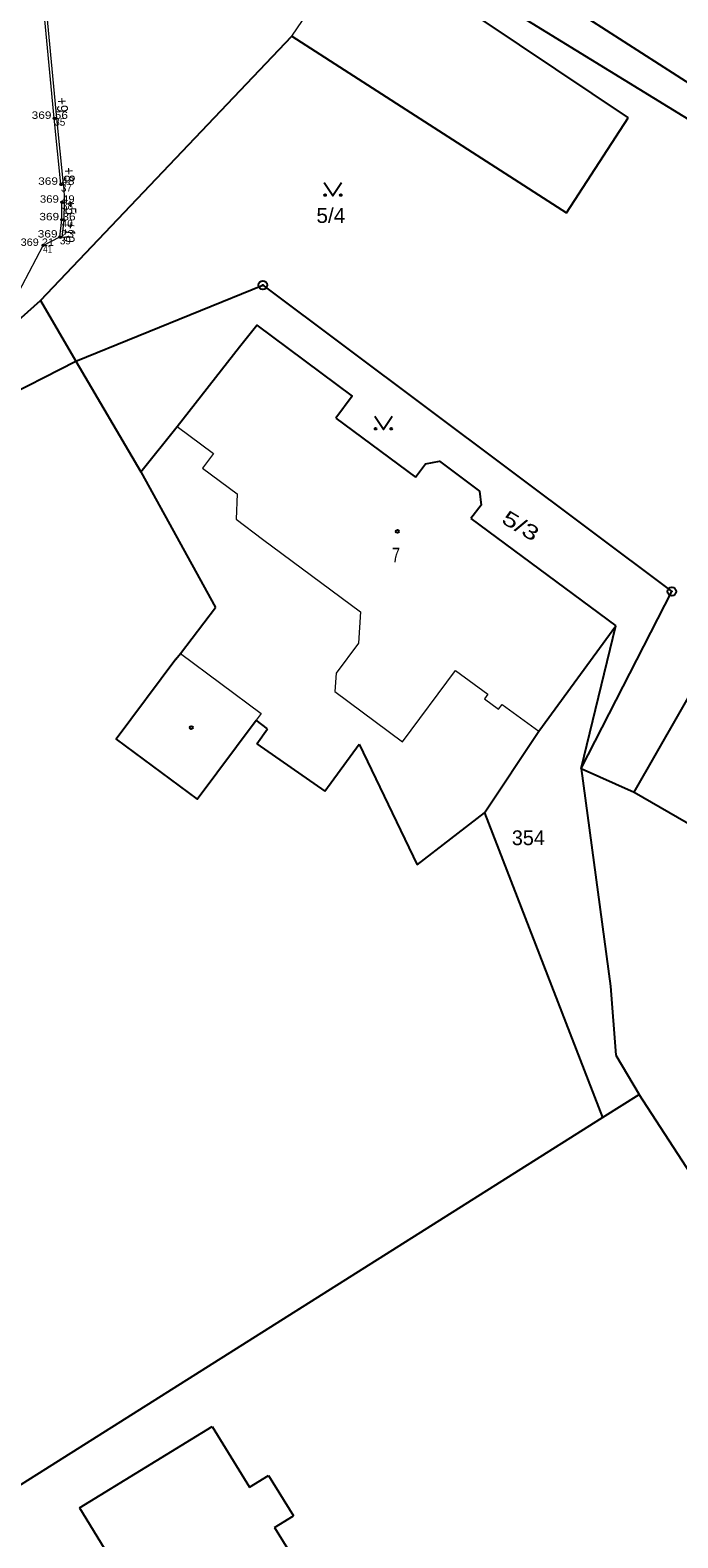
# Model space of a CAD drawing. Extents: x -592965 to -592390, y -1145071 to -1144631.
# Drawn here: x -592631.3 to -592594.1, y -1144880.5 to -1144793.9 of the extents above; entities that cross this region are included whole.
import ezdxf
from ezdxf.enums import TextEntityAlignment as Align

# ---------------------------------------------------------------- set-up
doc = ezdxf.new("R2010")
doc.units = 0
doc.header["$LTSCALE"] = 0.17
doc.header["$PDMODE"] = 32
doc.header["$PDSIZE"] = 0.085
for name, color, linetype, lineweight in [('1', 7, 'Continuous', 13), ('3', 7, 'Continuous', 13), ('4', 7, 'Continuous', 25)]:
    doc.layers.add(name, color=color, linetype=linetype, lineweight=lineweight)
doc.layers.add('2', color=7, linetype='Continuous')

msp = doc.modelspace()

# ---------------------------------------------------------------- linework, layer by layer
at = {"layer": '1'}
for p, q in [((-592629.46, -1144803.74), (-592629.32, -1144803.74)), ((-592629.58, -1144805.74), (-592629.44, -1144805.76))]:
    msp.add_line(p, q, dxfattribs=at)
for points in [[(-592629.52, -1144802.71), (-592629.9, -1144798.92), (-592630.78, -1144789.6), (-592630.89, -1144787.59)], [(-592629.38, -1144802.7), (-592629.76, -1144798.91), (-592630.64, -1144789.59), (-592630.75, -1144787.6)], [(-592629.52, -1144802.71), (-592629.38, -1144802.7), (-592629.32, -1144803.74)], [(-592629.58, -1144805.74), (-592629.47, -1144804.75), (-592629.46, -1144803.74)], [(-592629.44, -1144805.76), (-592629.33, -1144804.76), (-592629.32, -1144803.74)], [(-592641.79, -1144908.72), (-592641.16, -1144902.38), (-592640.38, -1144895.02), (-592640.15, -1144889.82), (-592640.65, -1144883.36), (-592641.29, -1144877.49), (-592642.3, -1144871.74), (-592643.21, -1144867.79), (-592644.53, -1144861.22), (-592645.89, -1144855.01), (-592647.22, -1144849.42), (-592648.49, -1144841.98), (-592649.04, -1144837.88), (-592648.65, -1144833.94), (-592647.63, -1144830.74), (-592645.94, -1144827.26), (-592642.72, -1144822.58), (-592638.67, -1144817.55), (-592634.67, -1144812.8), (-592632.14, -1144809.3), (-592630.54, -1144806.22), (-592629.58, -1144805.74)]]:
    msp.add_lwpolyline(points, dxfattribs=at)
at = {"layer": '2'}
for p in [(-592629.9, -1144798.92), (-592629.52, -1144802.71), (-592629.46, -1144803.74), (-592629.47, -1144804.75), (-592629.58, -1144805.74), (-592630.54, -1144806.22)]:
    msp.add_point(p, dxfattribs=at)
at = {"layer": '3'}
for centre, radius in [((-592629.9001, -1144798.9199), 0.0625), ((-592629.9001, -1144798.9199), 0.0395), ((-592629.9001, -1144798.9199), 0.0125), ((-592629.5201, -1144802.7099), 0.0625), ((-592629.5201, -1144802.7099), 0.0395), ((-592629.5201, -1144802.7099), 0.0125), ((-592629.4601, -1144803.7399), 0.0625), ((-592629.4601, -1144803.7399), 0.0395), ((-592629.4601, -1144803.7399), 0.0125), ((-592629.4701, -1144804.7499), 0.0625), ((-592629.4701, -1144804.7499), 0.0395), ((-592629.4701, -1144804.7499), 0.0125), ((-592629.5801, -1144805.7399), 0.0625), ((-592629.5801, -1144805.7399), 0.0395), ((-592629.5801, -1144805.7399), 0.0125), ((-592630.5401, -1144806.2199), 0.0625), ((-592630.5401, -1144806.2199), 0.0395), ((-592630.5401, -1144806.2199), 0.0125)]:
    msp.add_circle(centre, radius, dxfattribs=at)
at = {"layer": '4'}
for p, q in [((-592630.17, -1144773.28), (-592589.61, -1144799.37)), ((-592613.84, -1144786.45), (-592586.25, -1144803.41)), ((-592612.39, -1144788.53), (-592596.93, -1144798.89)), ((-592630.7, -1144809.39), (-592616.26, -1144794.19)), ((-592616.26, -1144794.19), (-592600.47, -1144804.36)), ((-592600.47, -1144804.36), (-592596.93, -1144798.89)), ((-592628.66, -1144812.88), (-592617.92, -1144808.5)), ((-592617.92, -1144808.5), (-592594.42, -1144826.11)), ((-592644.25, -1144821.53), (-592630.7, -1144809.39)), ((-592630.7, -1144809.39), (-592628.66, -1144812.88)), ((-592622.84, -1144816.63), (-592619.26, -1144812.06)), ((-592635.23, -1144816.23), (-592628.66, -1144812.88)), ((-592628.66, -1144812.88), (-592624.93, -1144819.23)), ((-592624.93, -1144819.23), (-592622.84, -1144816.63)), ((-592613.73, -1144816.16), (-592609.15, -1144819.55)), ((-592624.93, -1144819.23), (-592620.63, -1144827.03)), ((-592605.96, -1144821.92), (-592597.64, -1144828.08)), ((-592599.63, -1144836.29), (-592594.42, -1144826.11)), ((-592602.06, -1144834.13), (-592597.64, -1144828.08)), ((-592599.63, -1144836.29), (-592597.64, -1144828.08)), ((-592596.58, -1144837.65), (-592592.65, -1144830.79)), ((-592617.65, -1144834.01), (-592618.31, -1144833.51)), ((-592618.27, -1144834.86), (-592617.65, -1144834.01)), ((-592605.19, -1144838.83), (-592602.06, -1144834.13)), ((-592618.27, -1144834.86), (-592614.36, -1144837.58)), ((-592614.36, -1144837.58), (-592612.39, -1144834.88)), ((-592612.39, -1144834.88), (-592609.05, -1144841.82)), ((-592599.63, -1144836.29), (-592597.94, -1144848.8)), ((-592599.63, -1144836.29), (-592596.58, -1144837.65)), ((-592596.58, -1144837.65), (-592589.79, -1144841.58)), ((-592609.05, -1144841.82), (-592605.19, -1144838.83)), ((-592605.19, -1144838.83), (-592598.41, -1144856.35)), ((-592597.94, -1144848.8), (-592597.63, -1144852.76)), ((-592597.63, -1144852.76), (-592596.3, -1144855.01)), ((-592598.41, -1144856.35), (-592596.3, -1144855.01)), ((-592583.07, -1144875.42), (-592596.3, -1144855.01)), ((-592635.02, -1144879.44), (-592598.41, -1144856.35)), ((-592628.45, -1144878.77), (-592620.83, -1144874.09)), ((-592620.83, -1144874.09), (-592618.68, -1144877.58)), ((-592618.68, -1144877.58), (-592617.59, -1144876.91)), ((-592617.59, -1144876.91), (-592616.16, -1144879.24)), ((-592628.45, -1144878.77), (-592621.96, -1144889.35)), ((-592617.24, -1144879.9), (-592616.16, -1144879.24)), ((-592617.24, -1144879.9), (-592614.27, -1144884.71))]:
    msp.add_line(p, q, dxfattribs=at)
at = {"layer": '4', "lineweight": 13}
for p, q in [((-592616.26, -1144794.19), (-592612.39, -1144788.53)), ((-592622.84, -1144816.63), (-592620.75, -1144818.18)), ((-592617.93, -1144823.1), (-592612.31, -1144827.29))]:
    msp.add_line(p, q, dxfattribs=at)
at = {"layer": '4'}
for points in [[(-592613.39, -1144802.63), (-592613.89, -1144803.38), (-592614.39, -1144802.63)], [(-592619.26, -1144812.06), (-592618.27, -1144810.8), (-592612.78, -1144814.89), (-592613.73, -1144816.16)], [(-592610.49, -1144816.06), (-592610.99, -1144816.81), (-592611.49, -1144816.06)], [(-592609.15, -1144819.55), (-592608.57, -1144818.77), (-592607.77, -1144818.62), (-592605.46, -1144820.34), (-592605.38, -1144821.15), (-592605.96, -1144821.92)], [(-592622.91, -1144830.01), (-592622.65, -1144829.67), (-592620.63, -1144827.03)], [(-592622.91, -1144830.01), (-592626.34, -1144834.59), (-592621.69, -1144838.05), (-592618.31, -1144833.51)]]:
    msp.add_lwpolyline(points, dxfattribs=at)
at = {"layer": '4', "lineweight": 13}
for points in [[(-592620.75, -1144818.18), (-592621.38, -1144819.02), (-592619.39, -1144820.5), (-592619.46, -1144821.96), (-592617.93, -1144823.1)], [(-592612.31, -1144827.29), (-592612.43, -1144829.09), (-592613.71, -1144830.81), (-592613.79, -1144831.85), (-592609.9, -1144834.75), (-592606.85, -1144830.66)], [(-592622.65, -1144829.67), (-592618.02, -1144833.12), (-592618.31, -1144833.51)], [(-592606.85, -1144830.66), (-592604.99, -1144832.01), (-592605.19, -1144832.29), (-592604.38, -1144832.88), (-592604.17, -1144832.6), (-592602.06, -1144834.13)]]:
    msp.add_lwpolyline(points, dxfattribs=at)
at = {"layer": '4'}
for centre, radius in [((-592614.34, -1144803.33), 0.05), ((-592613.44, -1144803.33), 0.05), ((-592617.92, -1144808.5), 0.25), ((-592617.92, -1144808.5), 0.0164), ((-592611.44, -1144816.76), 0.05), ((-592610.54, -1144816.76), 0.05), ((-592610.19, -1144822.66), 0.0875), ((-592594.42, -1144826.11), 0.25), ((-592594.42, -1144826.11), 0.0164), ((-592622.03, -1144833.93), 0.0875)]:
    msp.add_circle(centre, radius, dxfattribs=at)

# ---------------------------------------------------------------- texts
at = {"layer": '1'}
for s, rotation, width, p in [('+9', 273.164, 0.9, (-592629.7484, -1144798.1644)), ('+8', 273.164, 0.9, (-592629.3584, -1144802.1744)), ('+5', 273.164, 0.9, (-592629.2684, -1144804.0544)), ('+10', 263.723, 0.85, (-592629.3022, -1144805.4306))]:
    msp.add_text(s, height=0.62, rotation=rotation, dxfattribs=dict(at, width=width)).set_placement(p, align=Align.CENTER)
at = {"layer": '2'}
for s, p in [('35', (-592629.9, -1144799.345)), ('37', (-592629.52, -1144803.135)), ('38', (-592629.46, -1144804.165)), ('40', (-592629.47, -1144805.175)), ('39', (-592629.58, -1144806.165))]:
    msp.add_text(s, height=0.425, dxfattribs=at).set_placement(p)
at = {"layer": '2', "width": 0.8}
msp.add_text('41', height=0.425, dxfattribs=at).set_placement((-592630.54, -1144806.645))
at = {"layer": '3'}
for s, width, p in [('369 56', 1.2, (-592630.158, -1144798.95)), ('369 48', 1.2, (-592629.7845, -1144802.74)), ('369 49', 1.15, (-592629.7295, -1144803.77)), ('369 36', 1.2, (-592629.7175, -1144804.78)), ('369 23', 1.2, (-592629.8095, -1144805.77)), ('369 21', 1.1, (-592630.878, -1144806.25))]:
    msp.add_text(s, height=0.425, dxfattribs=dict(at, width=width)).set_placement(p, align=Align.CENTER)
at = {"layer": '4'}
for s, width, p in [('5/4', 1.05, (-592614.84, -1144804.93)), ('7', 0.75, (-592610.51, -1144824.44))]:
    msp.add_text(s, height=0.85, dxfattribs=dict(at, width=width)).set_placement(p)
at = {"layer": '4', "width": 1.4}
msp.add_text('5/3', height=0.85, rotation=329.049, dxfattribs=at).set_placement((-592604.27, -1144822.13))
at = {"layer": '4'}
msp.add_text('354', height=0.85, dxfattribs=at).set_placement((-592603.61, -1144840.69))

doc.saveas('drawing.dxf')
